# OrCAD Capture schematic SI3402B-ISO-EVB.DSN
size A; title: Si3402 Eval Board - Isolated; rev: 2.2; note: SI3402B-ISO-EVB
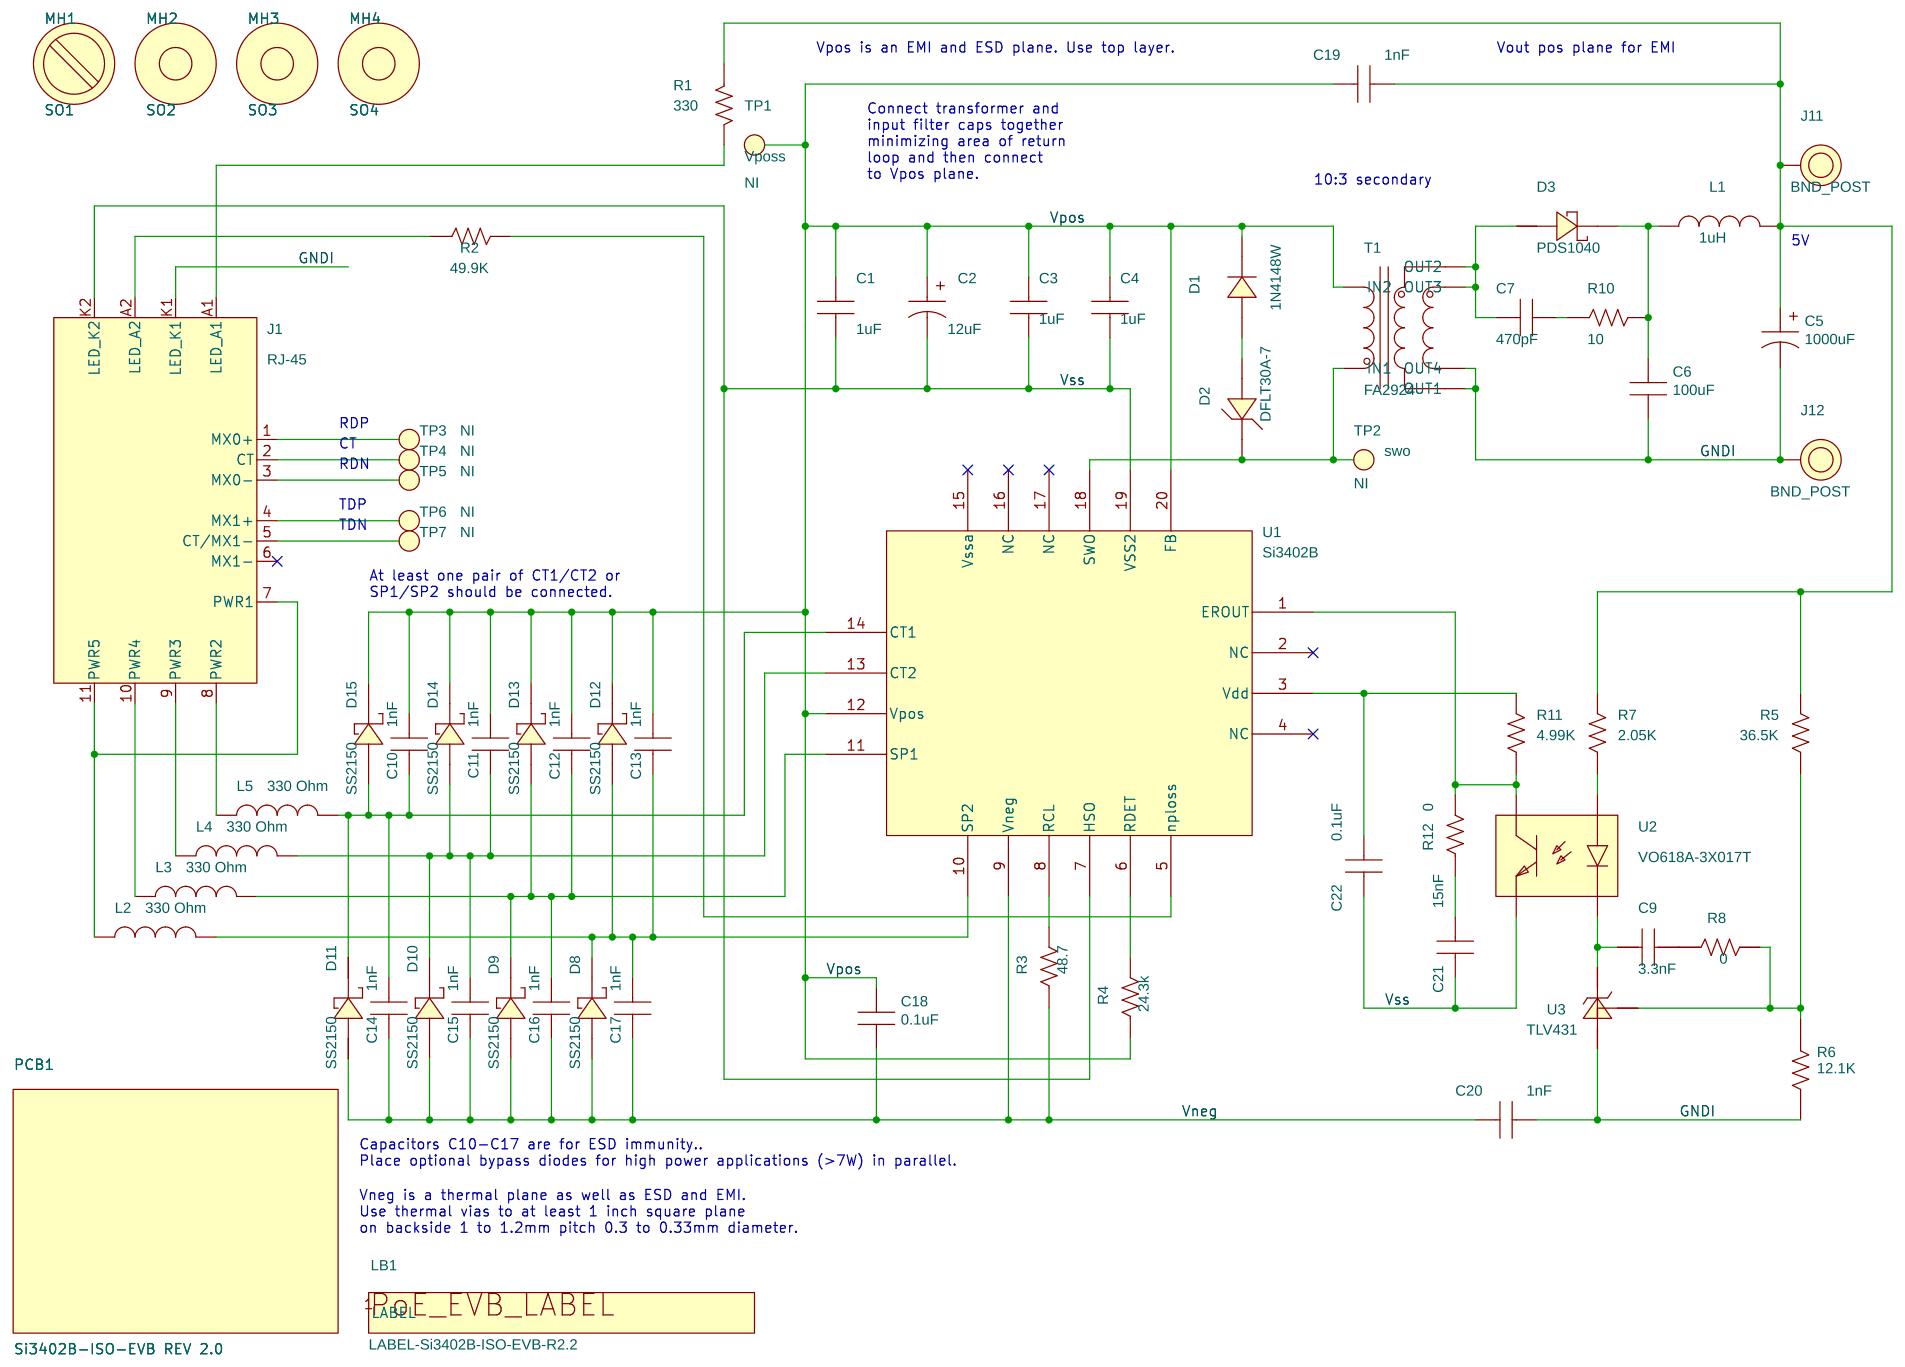
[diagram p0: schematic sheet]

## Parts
C1  1uF  [C1210]
C2  12uF  [C2.5X6.3MM-RAD]
C3  1uF  [C1210]
C4  1uF  [C1210]
C5  1000uF  [C3.5X8MM-RAD]
C6  100uF  [C1210]
C7  470pF  [C0805]
C9  3.3nF  [C0805]
C10  1nF  [C0603]
C11  1nF  [C0603]
C12  1nF  [C0603]
C13  1nF  [C0603]
C14  1nF  [C0603]
C15  1nF  [C0603]
C16  1nF  [C0603]
C17  1nF  [C0603]
C18  0.1uF  [C0805]
C19  1nF  [C1808]
C20  1nF  [C1808]
C21  15nF  [C0805]
C22  0.1uF  [C0805]
D1  1N4148W  [SOD123]
D2  DFLT30A-7  [POWERDI-123]
D3  PDS1040  [POWERDI-5]
D8  SS2150  [DO-214]
D9  SS2150  [DO-214]
D10  SS2150  [DO-214]
D11  SS2150  [DO-214]
D12  SS2150  [DO-214]
D13  SS2150  [DO-214]
D14  SS2150  [DO-214]
D15  SS2150  [DO-214]
J1  RJ-45  [RJ45-SI-52004]
J11  BND_POST  [BANANA-JACK]
J12  BND_POST  [BANANA-JACK]
L1  1uH  [IND-6.6X4.45MM]
L2  330 Ohm  [L0805]
L3  330 Ohm  [L0805]
L4  330 Ohm  [L0805]
L5  330 Ohm  [L0805]
LB1  LABEL-Si3402B-ISO-EVB-R2.2  [PTL-14-717]
MH1  4-40  [MH-125NP]
MH2  4-40  [MH-125NP]
MH3  4-40  [MH-125NP]
MH4  4-40  [MH-125NP]
PCB1  Si3402B-ISO-EVB REV 2.0  [N/A]
R1  330  [R0805]
R2  49.9K  [R0805]
R3  48.7  [R0805]
R4  24.3k  [R0805]
R5  36.5K  [R0805]
R6  12.1K  [R0805]
R7  2.05K  [R0603]
R8  0  [R0805]
R10  10  [R0805]
R11  4.99K  [R0805]
R12  0  [R0805]
SO1  STANDOFF
SO2  STANDOFF
SO3  STANDOFF
SO4  STANDOFF
T1  FA2924  [XFMR-FA2924]
TP1  BLACK  [TESTPOINT]
TP2  BLACK  [TESTPOINT]
TP3  BLACK  [TESTPOINT]
TP4  BLACK  [TESTPOINT]
TP5  BLACK  [TESTPOINT]
TP6  BLACK  [TESTPOINT]
TP7  BLACK  [TESTPOINT]
U1  Si3402B  [QFN20N5X5P0.8]
U2  VO618A-3X017T  [SO4N10.16P2.54-AKEC]
U3  TLV431  [TLV431-DBZ]

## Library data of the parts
C1 C3 C4 = CAP_NP: CAP, 1uF, 100V, ±10%, X7R, 1210; Manufacturer: Venkel; ManufacturerPN: C1210X7R101-105K; SiLabsPN: C1210X7R101-105K; Tolerance: ±10%; Type: X7R; Voltage: 100V; Datasheet: PID_C.pdf
C2 = CAP_POL_ALT: CAP, 12uF, 100V, ±20%, AL, 6.3X11.2MM; Manufacturer: Panasonic; ManufacturerPN: EEUFC2A120; SiLabsPN: EEUFC2A120; Tolerance: ±20%; Type: Alum_Elec; Voltage: 100V; Datasheet: ABA0000CE22.pdf
C5 = CAP_POL_ALT: CAP, 1000uF, 6.3V, ±20%, AL, 8X11.5MM; Manufacturer: Panasonic; ManufacturerPN: ECA0JM102; SiLabsPN: ECA0JM102; Tolerance: ±20%; Type: Alum_Elec; Voltage: 6.3V; Datasheet: ABA0000CE12.pdf
C6 = CAP_NP: CAP, 100uF, 6.3V, ±10%, X5R, 1210; Manufacturer: Venkel; ManufacturerPN: C1210X5R6R3-107K; SiLabsPN: C1210X5R6R3-107K; Tolerance: ±10%; Type: X5R; Voltage: 6.3V; Datasheet: PID_C.pdf
C7 = CAP_NP: CAP, 470pF, 50V, ±10%, X7R, 0805; Manufacturer: Venkel; ManufacturerPN: C0805X7R500-471K; SiLabsPN: C0805X7R500-471K; Tolerance: ±10%; Type: X7R; Voltage: 50V; Datasheet: PID_C.pdf
C9 = CAP_NP: CAP, 3.3nF, 16V, ±10%, X7R, 0805; Manufacturer: Venkel; ManufacturerPN: C0805X7R160-332K; SiLabsPN: C0805X7R160-332K; Tolerance: ±10%; Type: X7R; Voltage: 16V; Datasheet: PID_C.pdf
C10-C17 = CAP_NP: CAP, 1nF, 100V, ±10%, X7R, 0603; Manufacturer: Venkel; ManufacturerPN: C0603X7R101-102K; SiLabsPN: C0603X7R101-102K; Tolerance: ±10%; Type: X7R; Voltage: 100V; Datasheet: PID_C.pdf
C18 = CAP_NP: CAP, 0.1uF, 100V, ±10%, X7R, 0805; Manufacturer: Venkel; ManufacturerPN: C0805X7R101-104K; SiLabsPN: C0805X7R101-104K; Tolerance: ±10%; Type: X7R; Voltage: 100V; Datasheet: PID_C.pdf
C19 C20 = CAP_NP: CAP, 1nF, 3000V, ±10%, X7R, 1808; Manufacturer: Venkel; ManufacturerPN: C1808X7R302-102K; SiLabsPN: C1808X7R302-102K; Tolerance: ±10%; Type: X7R; Voltage: 3000V; Datasheet: PID_C.pdf
C21 = CAP_NP: CAP, 15nF, 16V, ±10%, X7R, 0805; Manufacturer: Venkel; ManufacturerPN: C0805X7R160-153K; SiLabsPN: C0805X7R160-153K; Tolerance: ±10%; Type: X7R; Voltage: 16V; Datasheet: PID_C.pdf
C22 = CAP_NP: CAP, 0.1uF, 16V, ±10%, X7R, 0805; Manufacturer: Venkel; ManufacturerPN: C0805X7R160-104K; SiLabsPN: C0805X7R160-104K; Tolerance: ±10%; Type: X7R; Voltage: 16V; Datasheet: PID_C.pdf
D1 = DIODE: DIO, fAST, 100V, 2A, SOD123; Manufacturer: Diodes Inc; Rating: 2A; Type: Fast; Voltage: 100V; Datasheet: ds30086-60872.pdf
D2 = DIODE_ZENER: DIO, ZENER, 30V, 4.65A, powerdi-123; Manufacturer: Diodes Inc.; Rating: 4.65A; Type: Zener; Voltage: 30V; Datasheet: ds30581-62296.pdf
D3 = DIODE_SCHOTTKY_DUAL_ANODE_3PIN: DIO, SCHOTTKY, 40V, 10A, POWERDI-5; Manufacturer: Diodes Inc.; ManufacturerPN: PDS1040-13; Rating: 10A; SiLabsPN: PDS1040-13; Type: Schottky; Voltage: 40V; Datasheet: ds30538-79818.pdf
D8-D15 = DIODE_SCHOTTKY: DIO, SINGLE, 150V, 2A, DO-214; Manufacturer: MCC; ManufacturerPN: SS2150-LTP; Rating: 2A; SiLabsPN: SS2150-LTP; Type: Single; Voltage: 150V; Datasheet: SS22-L-SS2150-L(DO-214)-478019.pdf
J1 = MAGJACK_3: CONN, RJ-45, MAGJACK, 1 Port PoE; Manufacturer: Bel; ManufacturerPN: SI-52003-F; SiLabsPN: SI-52003-F; Type: Receptacle; Datasheet: SI-52003-F.pdf
J11 = BINDING-POST: CONN, BANANA JACK, Threaded uninsulated; Manufacturer: ABBATRON HH SMITH; ManufacturerPN: 101; Rating: 15A; SiLabsPN: 101; Silk: +; Type: BANANA; Datasheet: SD-101.pdf
J12 = BINDING-POST: CONN, BANANA JACK, Threaded uninsulated; Manufacturer: ABBATRON HH SMITH; ManufacturerPN: 101; Rating: 15A; SiLabsPN: 101; Type: BANANA; Datasheet: SD-101.pdf
L1 = INDUCTOR: INDUCTOR, POWER, 1uH; Manufacturer: Coilcraft; ManufacturerPN: DO1608C-102ML_; Rating: 2.9A; SiLabsPN: DO1608C-102ML_; Tolerance: ±20%; Type: Shielded; Datasheet: do1608c.pdf
L2-L5 = Ferrite_Bead: FERRITE BEAD, 330 Ohm @100MHZ, 0805; Manufacturer: MuRata; ManufacturerPN: BLM21PG331SN1; Rating: 1500mA; SiLabsPN: BLM21PG331SN1; Type: SMT; Datasheet: Murata BLM Ferrites.pdf
LB1 = PoE_EVB_Label: LABEL, PDB, POLYIMIDE, WHITE, 1.00 in. X 0.187 in., FONT 2; Manufacturer: Skyworks; Type: POLYIMIDE, WHITE; Datasheet: Brady TLS2200 Label PTL-14-717.pdf
MH1-MH4 = SCREW-Small: HDW, SCREW, 4-40 x 1/4 in. Pan Head, Slotted, Nylon; Manufacturer: Richco Plastic Co; ManufacturerPN: NSS-4-4-01; SiLabsPN: NSS-4-4-01; Type: SCREW; Datasheet: RichcoPlasticCo_Screws.pdf
PCB1 = PCB: PCB, BARE BOARD, Si3402B-ISO-EVB REV 2.0; Manufacturer: Skyworks; Type: BARE PCB
R1 = RES: RES, 330 Ohm, 1/10W, ±1%, ThickFilm, 0805; Manufacturer: Venkel; ManufacturerPN: CR0805-10W-3300F; Rating: 1/10W; SiLabsPN: CR0805-10W-3300F; Tolerance: ±1%; Type: ThickFilm; Datasheet: PID_CR.pdf
R2 = RES: RES, 49.9K, 1/10W, ±1%, ThickFilm, 0805; Manufacturer: Venkel; ManufacturerPN: CR0805-10W-4992F; Rating: 1/10W; SiLabsPN: CR0805-10W-4992F; Tolerance: ±1%; Type: ThickFilm; Datasheet: PID_CR.pdf
R3 = RES: RES, 48.7 Ohm, 1/8W, ±1%, ThickFilm, 0805; Manufacturer: vishay; ManufacturerPN: CRCW080548R7FKTA; Rating: 1/8W; SiLabsPN: CR0805-8W-48R7F; Tolerance: ±1%; Type: ThickFilm; Datasheet: dcrcwe3-109170.pdf
R4 = RES: RES, 24.3k, 1/8W, ±1%, ThickFilm, 0805; Manufacturer: vishay; ManufacturerPN: CRCW080524K3FKEA; Rating: 1/8W; SiLabsPN: CR0805-8W-2432F; Tolerance: ±1%; Type: ThickFilm; Datasheet: dcrcwe3-109170.pdf
R5 = RES: RES, 36.5K, 1/10W, ±1%, ThickFilm, 0805; Manufacturer: Venkel; ManufacturerPN: CR0805-10W-3652F; Rating: 1/10W; SiLabsPN: CR0805-10W-3652F; Tolerance: ±1%; Type: ThickFilm; Datasheet: PID_CR.pdf
R6 = R: RES, 12.1K, 1/10W, ±1%, ThickFilm, 0805; Manufacturer: Venkel; ManufacturerPN: CR0805-10W-1212F; Rating: 1/10W; SiLabsPN: CR0805-10W-1212F; Tolerance: ±1%; Type: ThickFilm; Datasheet: PID_CR.pdf
R7 = RES: RES, 2.05K, 1/16W, ±1%, ThickFilm, 0603; Manufacturer: Venkel; ManufacturerPN: CR0603-16W-2051F; Rating: 1/16W; SiLabsPN: CR0603-16W-2051F; Tolerance: ±1%; Type: ThickFilm; Datasheet: PID_CR.pdf
R8 R12 = RES: RES, 0 Ohm, 2A, ThickFilm, 0805; Manufacturer: Venkel; ManufacturerPN: CR0805-10W-000; Rating: 2A; SiLabsPN: CR0805-10W-000; Type: ThickFilm; Datasheet: PID_CR.pdf
R10 = RES: RES, 10 Ohm, 1/10W, ±1%, ThickFilm, 0805; Manufacturer: Venkel; ManufacturerPN: CR0805-10W-10R0F; Rating: 1/10W; SiLabsPN: CR0805-10W-10R0F; Tolerance: ±1%; Type: ThickFilm; Datasheet: PID_CR.pdf
R11 = RES: RES, 4.99K, 1/10W, ±1%, ThickFilm, 0805; Manufacturer: Venkel; ManufacturerPN: CR0805-10W-4991F; Rating: 1/10W; SiLabsPN: CR0805-10W-4991F; Tolerance: ±1%; Type: ThickFilm; Datasheet: PID_CR.pdf
SO1-SO4 = STANDOFF: HDW, STANDOFF, 4-40 X 1/2" , Nylon; Manufacturer: SPC Technology; ManufacturerPN: 2397; SiLabsPN: 2397; Datasheet: SPC_Technology_spacers.pdf
T1 = XFMR_FA2805: TRANSFORMER, Flyback, 3.3V; Manufacturer: Coilcraft; ManufacturerPN: FA2924-AL; Part_Type: XFMR; SiLabsPN: FA2924-AL; Datasheet: fa2805.pdf
TP1 = TEST_POINT: TESTPOINT, BLACK, 0.050" LOOP, PTH; Installed component: NI; Manufacturer: Keystone; ManufacturerPN: 5001; SiLabsPN: 5001; Silk: Vposs; Type: LOOP; Datasheet: Keystone_thm_datasheet.pdf
TP2 = TEST_POINT: TESTPOINT, BLACK, 0.050" LOOP, PTH; Installed component: NI; Manufacturer: Keystone; ManufacturerPN: 5001; SiLabsPN: 5001; Silk: swo; Type: LOOP; Datasheet: Keystone_thm_datasheet.pdf
TP3-TP7 = TEST_POINT: TESTPOINT, BLACK, 0.050" LOOP, PTH; Installed component: NI; Manufacturer: Keystone; ManufacturerPN: 5001; SiLabsPN: 5001; Silk: <Silk>; Type: LOOP; Datasheet: Keystone_thm_datasheet.pdf
U1 = Si3402B: IC, FULLY-INTEGRATED 802.3-COMPLIANT PD INTERFACE AND SWITCHING REGULATOR, QFN20; Manufacturer: Skyworks; Type: PD; Voltage: 100; Datasheet: Si3402Rev1_0.pdf
U2 = OPTOCOUPLER: PHOTOCOUPLER, 5300Vrms Isolation, 4-PIN SMD; Manufacturer: Vishay; Datasheet: vo618a-244754.pdf
U3 = SHUNT_REG: IC, ADJ PREC SHUNT REG LV SOT-23 Voltage-Output 1.24 ~ 6V; Manufacturer: TI; ManufacturerPN: TLV431BCDBZR; Part_Type: IC/VREG/LIN; SiLabsPN: TLV431BCDBZR; Type: SHUNT; Datasheet: tlv431a.pdf

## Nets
GNDI: C5.2 C6.2 C20.2 J1.K1(LED) J12.1(BP) R6.2 T1.9(OUT1) T1.10(OUT4) U3.A(Anode)
Vss: C1.1 C2.2 C3.1 C4.1 C21.2 C22.2 J1.K2(LED) U1.7(HSO) U1.19(VSS2) U2.E(EMITTER)
LABEL: LB1.1(LABEL)
Vneg: C14.1 C15.1 C16.1 C17.1 C18.2 C20.1 D8.A(ANODE) D9.A(ANODE) D10.A(ANODE) D11.A(ANODE) R3.1 U1.9(Vneg)
Vpos: C1.2 C2.1 C3.2 C4.2 C10.2 C11.2 C12.2 C13.2 C18.1 C19.1 D1.K(CATHODE) D12.K(CATHODE) D13.K(CATHODE) D14.K(CATHODE) D15.K(CATHODE) R4.1 T1.1(IN2) TP1.1(Point) U1.12(Vpos) U1.20(FB)
N59838: D2.K(CATHODE) T1.2(IN1) TP2.1(Point) U1.18(SWO)
N60010: C12.1 C16.2 D9.K(CATHODE) D13.A(ANODE) L3.2 U1.11(SP1)
N60190: R3.2 U1.8(RCL)
N82452: R5.1 R6.1 R8.2 U3.REF(VREF)
N94729: R11.1 R12.2 U1.1(EROUT) U2.C(COLLECTOR)
N203825: C22.1 R11.2 U1.3(Vdd)
N410995: C5.1 C19.2 J11.1(BP) L1.2 R1.1 R5.2 R7.2
N452369: C10.1 C14.2 D11.K(CATHODE) D15.A(ANODE) L5.2 U1.14(CT1)
N452836: C11.1 C15.2 D10.K(CATHODE) D14.A(ANODE) L4.2 U1.13(CT2)
N473599: J1.A2(LED) R2.1
N478603: R2.2 U1.5(nploss)
N607196: R4.2 U1.6(RDET)
N765753: C13.1 C17.2 D8.K(CATHODE) D12.A(ANODE) L2.2 U1.10(SP2)
N845233: C7.1 D3.A1(ANODE) D3.A2(ANODE) T1.7(OUT2) T1.8(OUT3)
N857543: C9.1 U2.K(CATHODE) U3.K(Cathode)
N915920: D1.A(ANODE) D2.A(ANODE)
N921627: C21.1 R12.1
N922209: R7.1 U2.A(ANODE)
N924596: C6.1 D3.K1(CATHODE) L1.1 R10.2
N931180: J1.2(CT) TP4.1(Point)
N931186: J1.3(MX0-) TP5.1(Point)
N931192: J1.4(MX1+) TP6.1(Point)
N931211: J1.5(CT/MX1-) TP7.1(Point)
N931235: J1.1(MX0+) TP3.1(Point)
N941723: C7.2 R10.1
N1422746: J1.8(PWR2) L5.1
N1422750: J1.9(PWR3) L4.1
N1422754: J1.10(PWR4) L3.1
N1422758: J1.7(PWR1) J1.11(PWR5) L2.1
N1451388: J1.A1(LED) R1.2
N1480915: C9.2 R8.1

Not connected (* = marked no-connect by the designer): J1 6(MX1-)*; U1 2(NC)* 4(NC)* 15(Vssa)* 16(NC)* 17(NC)*

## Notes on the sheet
- Vpos is an EMI and ESD plane. Use top layer.
- Vout pos plane for EMI
- Connect transformer and
  input filter caps together
  minimizing area of return
  loop and then connect
  to Vpos plane.
- 10:3 secondary
- 5V
- RDP
- CT
- RDN
- TDP
- TDN
- At least one pair of CT1/CT2 or
  SP1/SP2 should be connected.
- Capacitors C10-C17 are for ESD immunity..
  Place optional bypass diodes for high power applications (>7W) in parallel.
- Vneg is a thermal plane as well as ESD and EMI.
  Use thermal vias to at least 1 inch square plane
  on backside 1 to 1.2mm pitch 0.3 to 0.33mm diameter.
